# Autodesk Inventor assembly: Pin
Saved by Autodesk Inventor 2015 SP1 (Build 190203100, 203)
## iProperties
Created: 2011-06
Part Number: Pin
Document SubType Name: Assembly
Designer: Guilherme Augusto Franco de Souza
Mass: 25.4879 g
Surface Area: 15.3496 cm^2
Volume: 3.24687 cm^3
Density: 7.85 g/cm^3
Description: Steel - DIN-20CrMoS4
ClientObjectVersion: 1
Author: Guilherme Augusto Franco de Souza
Revision Number: 00
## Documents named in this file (2)
- E:\Visitor Experience Project\WSI2015 - Visitor Experience Project\#46- Sheet Metal Technology\01- 3D Models\Outodoor Heater\2- Assemblies\Roller\Design Accelerator\Shaft1.iam
- E:\Visitor Experience Project\WSI2015 - Visitor Experience Project\#46- Sheet Metal Technology\01- 3D Models\Outodoor Heater\2- Assemblies\Roller\Design Accelerator\Shaft1.ipt
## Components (1 placed, 1 different names)
1. Pin:1
